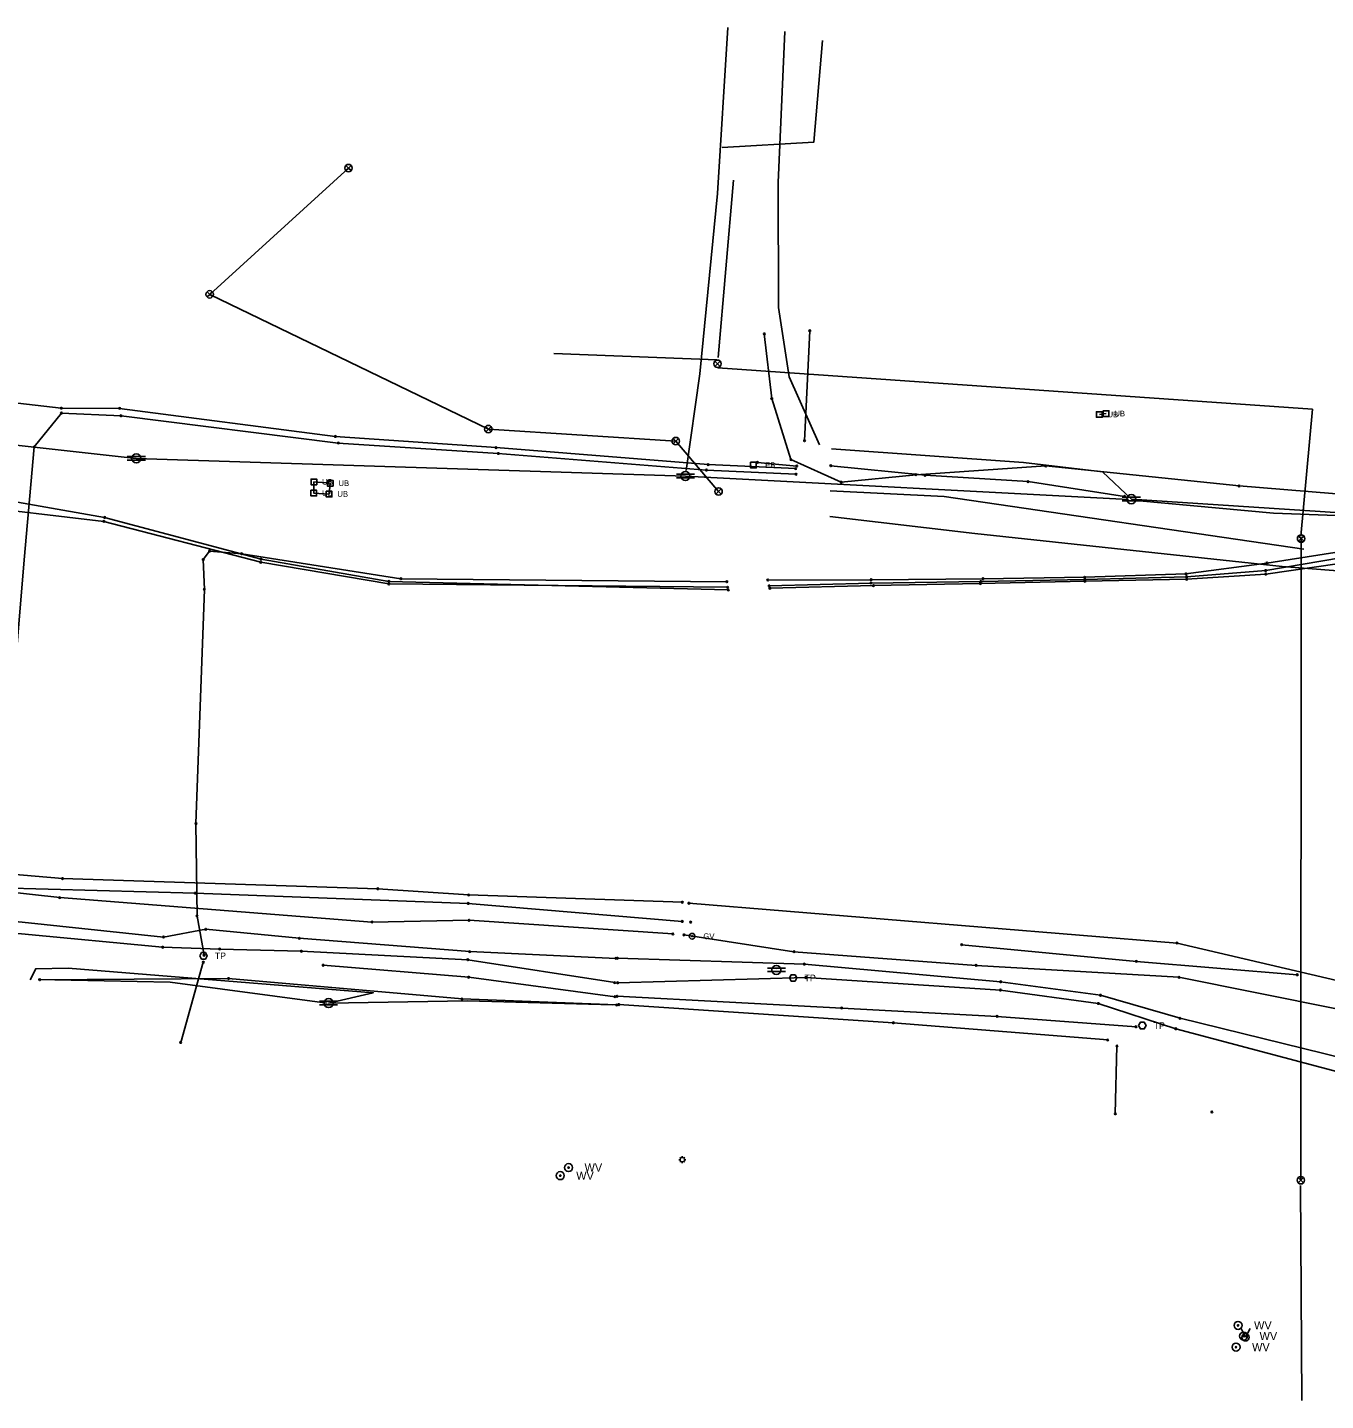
# Model space of a CAD drawing. Extents: x 20500343 to 20505311, y 7953484 to 7954193.
# Drawn here: x 20502424.8 to 20502739.5, y 7953660 to 7953993 of the extents above; entities that cross this region are included whole.
import ezdxf

# ---------------------------------------------------------------- set-up
doc = ezdxf.new("R2010")
doc.units = 0
for name, color, linetype in [('C-PROP-LINE-LOT', 7, 'Continuous'), ('V-ANNO-BNDY', 7, 'Continuous'), ('V-ANNO-NOTE', 7, 'Continuous'), ('V-CTRL-HVPT', 7, 'Continuous'), ('V-MON-FND', 7, 'Continuous'), ('V-SITE-FENC', 7, 'Continuous'), ('V-SSWR-STRC', 7, 'Continuous'), ('VF-NODE-MISC', 7, 'Continuous')]:
    doc.layers.add(name, color=color, linetype=linetype)

msp = doc.modelspace()

# ---------------------------------------------------------------- linework, layer by layer
at = {"layer": 'C-PROP-LINE-LOT'}
for p, q in [((20502592.29, 7953912.91), (20502595.99, 7953955.96)), ((20502591.95, 7953912.4), (20502552.43, 7953913.93)), ((20502733.81, 7953660.04), (20502733.43, 7953712.19))]:
    msp.add_line(p, q, dxfattribs=at)
for points in [[(20502594.62, 7953992.96), (20502592.06, 7953952.73), (20502587.81, 7953909), (20502584.53, 7953885.5)], [(20502617.58, 7953989.82), (20502615.49, 7953965.16), (20502593.22, 7953963.85)], [(20502616.8, 7953891.77), (20502609.45, 7953908.24), (20502606.9, 7953925.03), (20502606.83, 7953955.35), (20502608.4, 7953991.96)], [(20501786.53, 7953958.21), (20501802.89, 7953943.86), (20501839.77, 7953931.6), (20501880.96, 7953927.96), (20502018.29, 7953917.03), (20502077.19, 7953911.09), (20502142.41, 7953905.45), (20502199.08, 7953901.71), (20502241.51, 7953895.28), (20502292.25, 7953890.73), (20502324.65, 7953886.92), (20502369.24, 7953880.93), (20502409.05, 7953877.23), (20502443.31, 7953873.2), (20502481.36, 7953863.28), (20502512.4, 7953858.05), (20502594.55, 7953857.22)], [(20501786.53, 7953958.21), (20501798.37, 7953955.39), (20501845.31, 7953947.9), (20501861.48, 7953946.79), (20501912.59, 7953941.56), (20501926.87, 7953941.71), (20502019.52, 7953933.84), (20502080.36, 7953927.46), (20502107.02, 7953924.08), (20502144.15, 7953919.15), (20502174.11, 7953916.47), (20502211.46, 7953910.85), (20502243.75, 7953903.07), (20502293.11, 7953894.8), (20502325.39, 7953891.51), (20502370.1, 7953885.96), (20502409.42, 7953880.13), (20502443.48, 7953874.15), (20502481.41, 7953864.06), (20502512.42, 7953858.66), (20502594.72, 7953856.58)], [(20502502.62, 7953958.87), (20502468.96, 7953928.25), (20502536.54, 7953895.58), (20502581.98, 7953892.67), (20502592.37, 7953880.46)], [(20501927.57, 7953950.71), (20501980.32, 7953946.58), (20502008.33, 7953945.23), (20502082.1, 7953936.78), (20502144.41, 7953930.79), (20502205.22, 7953927.86), (20502265.66, 7953921.64), (20502325.14, 7953913.11), (20502432.98, 7953900.65), (20502447.13, 7953900.6), (20502499.42, 7953893.79), (20502538.42, 7953891.09), (20502589.85, 7953886.96), (20502611.07, 7953885.99)], [(20501941.48, 7953944.15), (20502193.58, 7953917.07), (20502451.16, 7953888.46), (20502584.33, 7953884.2), (20502691.76, 7953878.47)], [(20502613.21, 7953892.76), (20502614.47, 7953919.42)], [(20502603.44, 7953918.66), (20502605.26, 7953902.99), (20502609.92, 7953888.17), (20502622.1, 7953882.7), (20502640.25, 7953884.52), (20502671.71, 7953886.63), (20502718.58, 7953881.8), (20502764.86, 7953878.03), (20502844.74, 7953874.85), (20502922.16, 7953869.49), (20502923.06, 7953867.25)], [(20502733.57, 7953869.64), (20502736.34, 7953900.37), (20502592.19, 7953910.45)], [(20502415.71, 7953762.4), (20502419.47, 7953809.35), (20502423.95, 7953863.88), (20502426.43, 7953891.24), (20502433.02, 7953899.45), (20502447.47, 7953898.8), (20502500.14, 7953892.2), (20502538.94, 7953889.66), (20502589.43, 7953885.63), (20502611.13, 7953884.64)], [(20502619.78, 7953890.78), (20502666.32, 7953887.46), (20502685.45, 7953885.23), (20502692.45, 7953878.59)], [(20502611.33, 7953886.61), (20502601.78, 7953887.51)], [(20502619.57, 7953886.7), (20502642.44, 7953884.37), (20502667.42, 7953882.84), (20502690.79, 7953879.25)], [(20502619.43, 7953880.61), (20502647.07, 7953879.24), (20502734.3, 7953866.49)], [(20502692.45, 7953878.59), (20502942.15, 7953862.29), (20503185.94, 7953841.4)], [(20502694.42, 7953878.2), (20502726.94, 7953875.21), (20502770.34, 7953873.56), (20502805.65, 7953872.03), (20502892.71, 7953866.01), (20502921.42, 7953863.8)], [(20502619.3, 7953874.37), (20502654.48, 7953870.28), (20502729.02, 7953862.23), (20502796.55, 7953856.97), (20502877.1, 7953849.29), (20502920.79, 7953846.35), (20502948.65, 7953844.32)], [(20502604.3, 7953858.98), (20502629.37, 7953859.07), (20502656.51, 7953859.31), (20502681.15, 7953859.64), (20502705.7, 7953860.48), (20502725.32, 7953863.09), (20502743.33, 7953865.93), (20502765.13, 7953869.05), (20502788.54, 7953867.4), (20502823.08, 7953864.96), (20502865.42, 7953861.97), (20502909.13, 7953857.18), (20502921.96, 7953863.39)], [(20502604.63, 7953857.57), (20502629.33, 7953858.26), (20502655.96, 7953858.62), (20502681.16, 7953859.09), (20502705.87, 7953859.77), (20502725.04, 7953861.28), (20502743.18, 7953864.36), (20502761.47, 7953867.22), (20502788.32, 7953866.05), (20502823.3, 7953864.3), (20502865.74, 7953861.5), (20502909, 7953856.36), (20502922.72, 7953863.34)], [(20502604.8, 7953856.97), (20502629.91, 7953857.63), (20502655.82, 7953858.13), (20502681.23, 7953858.7), (20502705.86, 7953859.16), (20502725.06, 7953860.42), (20502742.94, 7953863.02), (20502761.73, 7953866.37), (20502788.18, 7953865.42), (20502823.26, 7953863.59), (20502865.72, 7953861.02), (20502908.79, 7953855.5), (20502923.38, 7953865.78)], [(20502733.61, 7953869.05), (20502733.56, 7953713.45)], [(20502594.37, 7953858.58), (20502515.33, 7953859.3), (20502476.73, 7953865.35), (20502468.93, 7953865.99), (20502467.39, 7953863.95), (20502467.68, 7953856.72), (20502465.63, 7953799.94), (20502465.89, 7953777.51), (20502467.62, 7953768.01)], [(20501822.69, 7953839.61), (20501870.85, 7953834.49), (20501955.49, 7953824.45), (20502075.53, 7953814.96), (20502170.68, 7953806.48), (20502238.89, 7953800.97), (20502334.58, 7953792.75), (20502432.59, 7953781.98), (20502508.31, 7953776.06), (20502531.87, 7953776.49), (20502581.28, 7953773.17)], [(20501871.18, 7953838.12), (20501950.16, 7953828.62), (20502076.03, 7953818.34), (20502154.77, 7953811.13), (20502239.61, 7953803.57), (20502335.63, 7953794.91), (20502433.27, 7953786.61), (20502509.73, 7953784.12), (20502531.75, 7953782.62), (20502583.58, 7953780.86)], [(20501766.01, 7953834.76), (20501821.75, 7953833.43), (20501869.61, 7953826.07), (20501921.27, 7953820.74), (20501975.38, 7953813.59), (20502027.18, 7953809.28), (20502096.84, 7953802.19), (20502149.48, 7953798.41), (20502206.76, 7953791.49), (20502246.02, 7953783), (20502332.45, 7953784.05), (20502423.49, 7953775.99), (20502457.77, 7953772.43), (20502468.01, 7953774.31), (20502490.69, 7953772.12), (20502532.01, 7953768.89), (20502567.5, 7953767.25)], [(20501765.8, 7953831.13), (20501934, 7953813.62), (20501986.76, 7953807.7), (20502096.89, 7953796.9), (20502224.25, 7953788.94), (20502278.96, 7953784.08), (20502408.88, 7953781.44), (20502417.83, 7953784.37), (20502465.46, 7953783.06), (20502531.65, 7953780.57), (20502583.55, 7953776.2)], [(20501923.78, 7953810.45), (20501976.29, 7953805.33), (20502027.19, 7953800.79), (20502097.04, 7953794.03), (20502148.61, 7953790.06), (20502191.57, 7953787.56), (20502246.17, 7953780.88), (20502423.34, 7953773.23), (20502457.56, 7953769.95), (20502471.39, 7953769.52), (20502491.18, 7953768.99), (20502531.55, 7953766.92), (20502567.17, 7953761.38)], [(20502585.16, 7953780.62), (20502703.53, 7953770.96), (20502778.6, 7953753.43), (20502855.95, 7953745.33), (20502958.04, 7953735.55), (20503064.82, 7953724.97), (20503167.9, 7953714.97), (20503186.63, 7953713.33), (20503187.62, 7953709.92)], [(20502583.99, 7953772.95), (20502610.65, 7953768.87), (20502654.81, 7953765.56), (20502704, 7953762.66), (20502780.84, 7953747.28), (20502856.1, 7953741.6), (20502958.12, 7953733.02), (20503064.96, 7953721.73), (20503167.51, 7953711.49), (20503200.31, 7953708.91), (20503261.33, 7953704.35), (20503308.48, 7953700.62), (20503425.37, 7953689.03), (20503525.59, 7953683.92), (20503632.36, 7953675.44)], [(20502651.32, 7953770.56), (20502693.68, 7953766.53), (20502732.67, 7953763.27)], [(20502467.41, 7953766.32), (20502461.93, 7953746.86)], [(20502567.82, 7953767.29), (20502613.16, 7953765.86), (20502660.75, 7953761.57), (20502684.96, 7953758.32), (20502704.25, 7953752.73), (20502749.31, 7953741.65), (20502800.87, 7953733.72), (20502861.3, 7953730.84), (20502920.69, 7953724.3), (20502983.15, 7953721.6), (20503039.18, 7953715.3), (20503094.87, 7953710.44), (20503155.33, 7953704.72), (20503201.09, 7953699.55), (20503255.71, 7953694.61), (20503304.33, 7953690.28), (20503344.16, 7953687.19), (20503374.46, 7953685.7), (20503426.83, 7953682.97), (20503524.49, 7953672.95), (20503631.72, 7953664.81)], [(20502425.4, 7953762.06), (20502426.79, 7953764.73), (20502434.63, 7953764.91), (20502508.61, 7953758.91), (20502497.79, 7953756.4), (20502531.51, 7953756.93), (20502566.72, 7953755.98)], [(20502496.48, 7953765.6), (20502531.78, 7953762.69), (20502567.26, 7953757.96)], [(20502427.37, 7953762.15), (20502459.38, 7953761.52), (20502497.41, 7953756.43)], [(20502427.77, 7953762.08), (20502473.54, 7953762.37), (20502530.15, 7953757.41), (20502567.64, 7953755.96)], [(20502567.9, 7953761.34), (20502613.51, 7953762.6), (20502660.72, 7953759.56), (20502684.44, 7953756.31), (20502703.23, 7953750.18), (20502747.73, 7953738.37), (20502800.44, 7953730.37), (20502860.52, 7953724.51), (20502919.86, 7953720.87), (20502983.04, 7953717.79), (20503038.66, 7953709.78), (20503094.29, 7953705.56), (20503153.13, 7953700.69), (20503201.01, 7953696.62), (20503255.42, 7953690.81), (20503303.52, 7953686.48), (20503344.16, 7953683.02), (20503374.14, 7953680.96), (20503426.87, 7953677.14), (20503523.93, 7953669.23), (20503630.84, 7953663.08)], [(20502567.77, 7953758.06), (20502622.22, 7953755.2), (20502659.9, 7953753.18), (20502693.6, 7953750.67)], [(20502568.16, 7953756.05), (20502634.72, 7953751.64), (20502686.73, 7953747.47)], [(20502688.97, 7953746.01), (20502688.56, 7953729.56)]]:
    msp.add_lwpolyline(points, dxfattribs=at)
at = {"layer": 'V-ANNO-BNDY'}
for p, q in [((20502691.18, 7953878.28), (20502691.18, 7953878.28)), ((20502585.6, 7953776.04), (20502585.6, 7953776.04)), ((20502606.39, 7953764.46), (20502606.39, 7953764.46)), ((20502711.98, 7953730.01), (20502711.98, 7953730.01))]:
    msp.add_line(p, q, dxfattribs=at)
for radius in [0.685, 0.114]:
    msp.add_circle((20502585.93, 7953772.61), radius, dxfattribs=at)
at = {"layer": 'V-ANNO-NOTE'}
for centre in [(20502614.47, 7953919.42), (20502603.44, 7953918.66), (20502605.26, 7953902.99), (20502432.98, 7953900.65), (20502433.02, 7953899.45), (20502447.13, 7953900.6), (20502447.47, 7953898.8), (20502499.42, 7953893.79), (20502613.21, 7953892.76), (20502426.43, 7953891.24), (20502500.14, 7953892.2), (20502538.42, 7953891.09), (20502538.94, 7953889.66), (20502589.85, 7953886.96), (20502601.78, 7953887.51), (20502609.92, 7953888.17), (20502611.07, 7953885.99), (20502611.33, 7953886.61), (20502619.57, 7953886.7), (20502671.71, 7953886.63), (20502589.43, 7953885.63), (20502611.13, 7953884.64), (20502622.1, 7953882.7), (20502640.25, 7953884.52), (20502642.44, 7953884.37), (20502667.42, 7953882.84), (20502690.79, 7953879.25), (20502718.58, 7953881.8), (20502443.31, 7953873.2), (20502443.48, 7953874.15), (20502468.93, 7953865.99), (20502467.39, 7953863.95), (20502476.73, 7953865.35), (20502481.36, 7953863.28), (20502481.41, 7953864.06), (20502725.32, 7953863.09), (20502515.33, 7953859.3), (20502656.51, 7953859.31), (20502681.15, 7953859.64), (20502705.7, 7953860.48), (20502705.87, 7953859.77), (20502725.04, 7953861.28), (20502725.06, 7953860.42), (20502467.68, 7953856.72), (20502512.4, 7953858.05), (20502512.42, 7953858.66), (20502594.37, 7953858.58), (20502594.55, 7953857.22), (20502594.72, 7953856.58), (20502604.3, 7953858.98), (20502604.63, 7953857.57), (20502604.8, 7953856.97), (20502629.33, 7953858.26), (20502629.37, 7953859.07), (20502629.91, 7953857.63), (20502655.82, 7953858.13), (20502655.96, 7953858.62), (20502681.16, 7953859.09), (20502681.23, 7953858.7), (20502705.86, 7953859.16), (20502465.63, 7953799.94), (20502433.27, 7953786.61), (20502465.46, 7953783.06), (20502509.73, 7953784.12), (20502432.59, 7953781.98), (20502531.65, 7953780.57), (20502531.75, 7953782.62), (20502583.58, 7953780.86), (20502585.16, 7953780.62), (20502465.89, 7953777.51), (20502508.31, 7953776.06), (20502531.87, 7953776.49), (20502583.55, 7953776.2), (20502585.6, 7953776.04), (20502468.01, 7953774.31), (20502581.28, 7953773.17), (20502583.99, 7953772.95), (20502457.56, 7953769.95), (20502457.77, 7953772.43), (20502471.39, 7953769.52), (20502490.69, 7953772.12), (20502651.32, 7953770.56), (20502703.53, 7953770.96), (20502467.41, 7953766.32), (20502467.62, 7953768.01), (20502491.18, 7953768.99), (20502531.55, 7953766.92), (20502532.01, 7953768.89), (20502567.5, 7953767.25), (20502567.82, 7953767.29), (20502610.65, 7953768.87), (20502693.68, 7953766.53), (20502496.48, 7953765.6), (20502613.16, 7953765.86), (20502654.81, 7953765.56), (20502732.67, 7953763.27), (20502427.77, 7953762.08), (20502473.54, 7953762.37), (20502531.78, 7953762.69), (20502567.17, 7953761.38), (20502567.9, 7953761.34), (20502613.51, 7953762.6), (20502660.72, 7953759.56), (20502660.75, 7953761.57), (20502704, 7953762.66), (20502530.15, 7953757.41), (20502567.26, 7953757.96), (20502567.77, 7953758.06), (20502684.44, 7953756.31), (20502684.96, 7953758.32), (20502567.64, 7953755.96), (20502568.16, 7953756.05), (20502622.22, 7953755.2), (20502659.9, 7953753.18), (20502704.25, 7953752.73), (20502634.72, 7953751.64), (20502693.6, 7953750.67), (20502703.23, 7953750.18), (20502461.93, 7953746.86), (20502686.73, 7953747.47), (20502688.97, 7953746.01), (20502688.56, 7953729.56), (20502711.98, 7953730.01)]:
    msp.add_circle(centre, 0.2, dxfattribs=at)
at = {"layer": 'V-CTRL-HVPT'}
for p, q in [((20502448.96, 7953888.9), (20502453.36, 7953888.9)), ((20502448.96, 7953888.02), (20502453.36, 7953888.02)), ((20502582.13, 7953884.65), (20502586.53, 7953884.65)), ((20502582.13, 7953883.77), (20502586.53, 7953883.77)), ((20502690.25, 7953879.04), (20502694.65, 7953879.04)), ((20502690.25, 7953878.16), (20502694.65, 7953878.16)), ((20502604.19, 7953764.91), (20502608.59, 7953764.91)), ((20502604.19, 7953764.03), (20502608.59, 7953764.03)), ((20502495.59, 7953756.84), (20502499.99, 7953756.84)), ((20502495.59, 7953755.96), (20502499.99, 7953755.96)), ((20502582.69, 7953718.44), (20502583.02, 7953718.44)), ((20502582.95, 7953719.06), (20502583.18, 7953718.83)), ((20502582.95, 7953717.83), (20502583.18, 7953718.06)), ((20502583.56, 7953719.31), (20502583.56, 7953718.99)), ((20502583.56, 7953717.9), (20502583.56, 7953717.57)), ((20502583.94, 7953718.83), (20502584.17, 7953719.06)), ((20502583.94, 7953718.06), (20502584.17, 7953717.83)), ((20502584.1, 7953718.44), (20502584.43, 7953718.44))]:
    msp.add_line(p, q, dxfattribs=at)
for centre, radius in [((20502451.16, 7953888.46), 1.1), ((20502584.33, 7953884.2), 1.1), ((20502692.45, 7953878.59), 1.1), ((20502606.39, 7953764.46), 1.1), ((20502497.79, 7953756.4), 1.1), ((20502583.56, 7953718.44), 0.543)]:
    msp.add_circle(centre, radius, dxfattribs=at)
at = {"layer": 'V-MON-FND'}
for points in [[(20502686.32, 7953899.33), (20502684.69, 7953899.11)], [(20502686.32, 7953899.33), (20502684.69, 7953899.11)], [(20502466.54, 7953767.87), (20502466.99, 7953768.66), (20502467.91, 7953768.66), (20502468.36, 7953767.87), (20502467.91, 7953767.08), (20502466.99, 7953767.08), (20502466.54, 7953767.87)], [(20502609.54, 7953762.5), (20502609.99, 7953763.29), (20502610.91, 7953763.29), (20502611.36, 7953762.5), (20502610.91, 7953761.7), (20502609.99, 7953761.7), (20502609.54, 7953762.5)], [(20502694.2, 7953750.95), (20502694.65, 7953751.75), (20502695.57, 7953751.75), (20502696.02, 7953750.95), (20502695.57, 7953750.16), (20502694.65, 7953750.16), (20502694.2, 7953750.95)]]:
    msp.add_lwpolyline(points, dxfattribs=at)
msp.add_lwpolyline([(20502497.92, 7953879.83), (20502494.2, 7953880.05), (20502494.23, 7953882.76), (20502498.19, 7953882.44)], close=True, dxfattribs=at)
msp.add_lwpolyline([(20502497.92, 7953879.83), (20502494.2, 7953880.05), (20502494.23, 7953882.76), (20502498.19, 7953882.44)], close=True, dxfattribs=at)
at = {"layer": 'V-SITE-FENC'}
for points in [[(20502684.69, 7953898.43), (20502684.69, 7953898.43), (20502685.38, 7953898.43), (20502685.38, 7953899.8), (20502684, 7953899.8), (20502684, 7953898.43), (20502684.69, 7953898.43)], [(20502686.32, 7953898.64), (20502686.32, 7953898.64), (20502687.01, 7953898.64), (20502687.01, 7953900.01), (20502685.63, 7953900.01), (20502685.63, 7953898.64), (20502686.32, 7953898.64)], [(20502600.82, 7953886.15), (20502600.82, 7953886.15), (20502601.51, 7953886.15), (20502601.51, 7953887.52), (20502600.13, 7953887.52), (20502600.13, 7953886.15), (20502600.82, 7953886.15)], [(20502494.23, 7953882.07), (20502494.23, 7953882.07), (20502494.92, 7953882.07), (20502494.92, 7953883.44), (20502493.54, 7953883.44), (20502493.54, 7953882.07), (20502494.23, 7953882.07)], [(20502498.19, 7953881.76), (20502498.19, 7953881.76), (20502498.88, 7953881.76), (20502498.88, 7953883.13), (20502497.5, 7953883.13), (20502497.5, 7953881.76), (20502498.19, 7953881.76)], [(20502494.2, 7953879.37), (20502494.2, 7953879.37), (20502494.89, 7953879.37), (20502494.89, 7953880.74), (20502493.51, 7953880.74), (20502493.51, 7953879.37), (20502494.2, 7953879.37)], [(20502497.92, 7953879.15), (20502497.92, 7953879.15), (20502498.61, 7953879.15), (20502498.61, 7953880.52), (20502497.23, 7953880.52), (20502497.23, 7953879.15), (20502497.92, 7953879.15)]]:
    msp.add_lwpolyline(points, dxfattribs=at)
at = {"layer": 'V-SSWR-STRC'}
for points in [[(20502501.98, 7953958.24), (20502502.62, 7953958.87), (20502501.98, 7953959.51)], [(20502503.26, 7953959.51), (20502502.62, 7953958.87), (20502503.26, 7953958.24)], [(20502468.32, 7953927.62), (20502468.96, 7953928.25), (20502468.32, 7953928.89)], [(20502469.6, 7953928.89), (20502468.96, 7953928.25), (20502469.6, 7953927.62)], [(20502591.46, 7953910.79), (20502592.1, 7953911.43), (20502591.46, 7953912.07)], [(20502592.74, 7953912.07), (20502592.1, 7953911.43), (20502592.74, 7953910.79)], [(20502535.9, 7953894.94), (20502536.54, 7953895.58), (20502535.9, 7953896.22)], [(20502537.18, 7953896.22), (20502536.54, 7953895.58), (20502537.18, 7953894.94)], [(20502581.34, 7953892.04), (20502581.98, 7953892.67), (20502581.34, 7953893.31)], [(20502582.62, 7953893.31), (20502581.98, 7953892.67), (20502582.62, 7953892.04)], [(20502591.73, 7953879.82), (20502592.37, 7953880.46), (20502591.73, 7953881.09)], [(20502593.01, 7953881.09), (20502592.37, 7953880.46), (20502593.01, 7953879.82)], [(20502732.97, 7953868.41), (20502733.61, 7953869.05), (20502732.97, 7953869.68)], [(20502732.97, 7953868.38), (20502733.61, 7953869.02), (20502732.97, 7953869.65)], [(20502734.25, 7953869.68), (20502733.61, 7953869.05), (20502734.25, 7953868.41)], [(20502734.25, 7953869.65), (20502733.61, 7953869.02), (20502734.25, 7953868.38)], [(20502732.92, 7953712.82), (20502733.56, 7953713.45), (20502732.92, 7953714.09)], [(20502734.2, 7953714.09), (20502733.56, 7953713.45), (20502734.2, 7953712.82)]]:
    msp.add_lwpolyline(points, dxfattribs=at)
for centre, radius in [((20502555.98, 7953716.53), 0.971), ((20502555.98, 7953716.53), 0.162), ((20502553.96, 7953714.57), 0.971), ((20502553.96, 7953714.57), 0.162), ((20502718.33, 7953678.27), 0.971), ((20502718.33, 7953678.27), 0.162), ((20502719.67, 7953675.68), 0.971), ((20502717.85, 7953672.99), 0.971), ((20502717.85, 7953672.99), 0.162), ((20502719.67, 7953675.68), 0.162)]:
    msp.add_circle(centre, radius, dxfattribs=at)
for centre, start, end in [((20502502.62, 7953958.87), 135, 225), ((20502502.62, 7953958.87), 45, 135), ((20502502.62, 7953958.87), 315, 45), ((20502502.62, 7953958.87), 225, 315), ((20502468.96, 7953928.25), 135, 225), ((20502468.96, 7953928.25), 45, 135), ((20502468.96, 7953928.25), 225, 315), ((20502468.96, 7953928.25), 315, 45), ((20502592.1, 7953911.43), 135, 225), ((20502592.1, 7953911.43), 45, 135), ((20502592.1, 7953911.43), 225, 315), ((20502592.1, 7953911.43), 315, 45), ((20502536.54, 7953895.58), 135, 225), ((20502536.54, 7953895.58), 45, 135), ((20502536.54, 7953895.58), 315, 45), ((20502536.54, 7953895.58), 225, 315), ((20502581.98, 7953892.67), 135, 225), ((20502581.98, 7953892.67), 45, 135), ((20502581.98, 7953892.67), 315, 45), ((20502581.98, 7953892.67), 225, 315), ((20502592.37, 7953880.46), 135, 225), ((20502592.37, 7953880.46), 45, 135), ((20502592.37, 7953880.46), 225, 315), ((20502592.37, 7953880.46), 315, 45), ((20502733.61, 7953869.05), 135, 225), ((20502733.61, 7953869.02), 135, 225), ((20502733.61, 7953869.05), 45, 135), ((20502733.61, 7953869.02), 45, 135), ((20502733.61, 7953869.05), 315, 45), ((20502733.61, 7953869.02), 315, 45), ((20502733.61, 7953869.05), 225, 315), ((20502733.61, 7953869.02), 225, 315), ((20502733.56, 7953713.45), 135, 225), ((20502733.56, 7953713.45), 45, 135), ((20502733.56, 7953713.45), 315, 45), ((20502733.56, 7953713.45), 225, 315)]:
    msp.add_arc(centre, 0.899, start, end, dxfattribs=at)
at = {"layer": 'VF-NODE-MISC'}
for p, q in [((20502719.07, 7953677.54), (20502720.15, 7953675.38)), ((20502720.15, 7953675.38), (20502721.23, 7953677.54))]:
    msp.add_line(p, q, dxfattribs=at)
msp.add_circle((20502720.15, 7953675.38), 0.897, dxfattribs=at)

# ---------------------------------------------------------------- texts
at = {"layer": 'V-ANNO-BNDY'}
msp.add_text('GV', height=1.399, dxfattribs=at).set_placement((20502588.67, 7953771.91))
at = {"layer": 'V-MON-FND'}
for p in [(20502470.19, 7953767.07), (20502613.19, 7953761.7), (20502697.85, 7953750.15)]:
    msp.add_text('TP', height=1.599, dxfattribs=at).set_placement(p)
at = {"layer": 'V-SITE-FENC'}
for s, p in [('UB', (20502686.68, 7953898.43)), ('UB', (20502688.31, 7953898.65)), ('EB', (20502603.66, 7953886.14)), ('UB', (20502496.22, 7953882.08)), ('UB', (20502500.18, 7953881.76)), ('UB', (20502496.19, 7953879.37)), ('UB', (20502499.91, 7953879.15))]:
    msp.add_text(s, height=1.399, dxfattribs=at).set_placement(p)
at = {"layer": 'V-SSWR-STRC'}
for p in [(20502559.86, 7953715.54), (20502557.84, 7953713.58), (20502722.21, 7953677.28), (20502723.55, 7953674.69), (20502721.73, 7953672)]:
    msp.add_text('WV', height=1.982, dxfattribs=at).set_placement(p)

doc.saveas('drawing.dxf')
